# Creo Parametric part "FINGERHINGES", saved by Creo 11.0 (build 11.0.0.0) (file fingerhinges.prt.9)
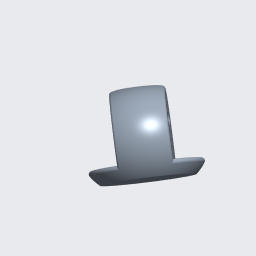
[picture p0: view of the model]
Units: Inch lbm Second (Pro/E Default); INCH, POUND, SECS

Created from: XX_INLBS_PART_SOLID_ABS.PRT

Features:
  1. datum plane "RIGHT"
  2. datum plane "TOP"
  3. datum plane "FRONT"
  4. coordinate system
  5. sketch "Sketch 1", "A_1"
  6. revolve "Revolve 1"
  7. datum plane "DTM1"
  8. sketch "Sketch 2"
  9. extruded cut "Extrude 1"
  10. mirror "Mirror 1"
  11. extruded cut "Extrude 1 (2)"
  12. round "Round 1"
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
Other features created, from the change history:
  sketch "Sketch 2" (2 times)
  extruded cut "Extrude 1"
  datum plane "DTM2"
  sketch "Sketch 3"
  extruded cut "Extrude 2"
  sketch "Sketch 4"
  extruded cut "Extrude 3"
  extrusion "Extrude 4"
  round "Round 2"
